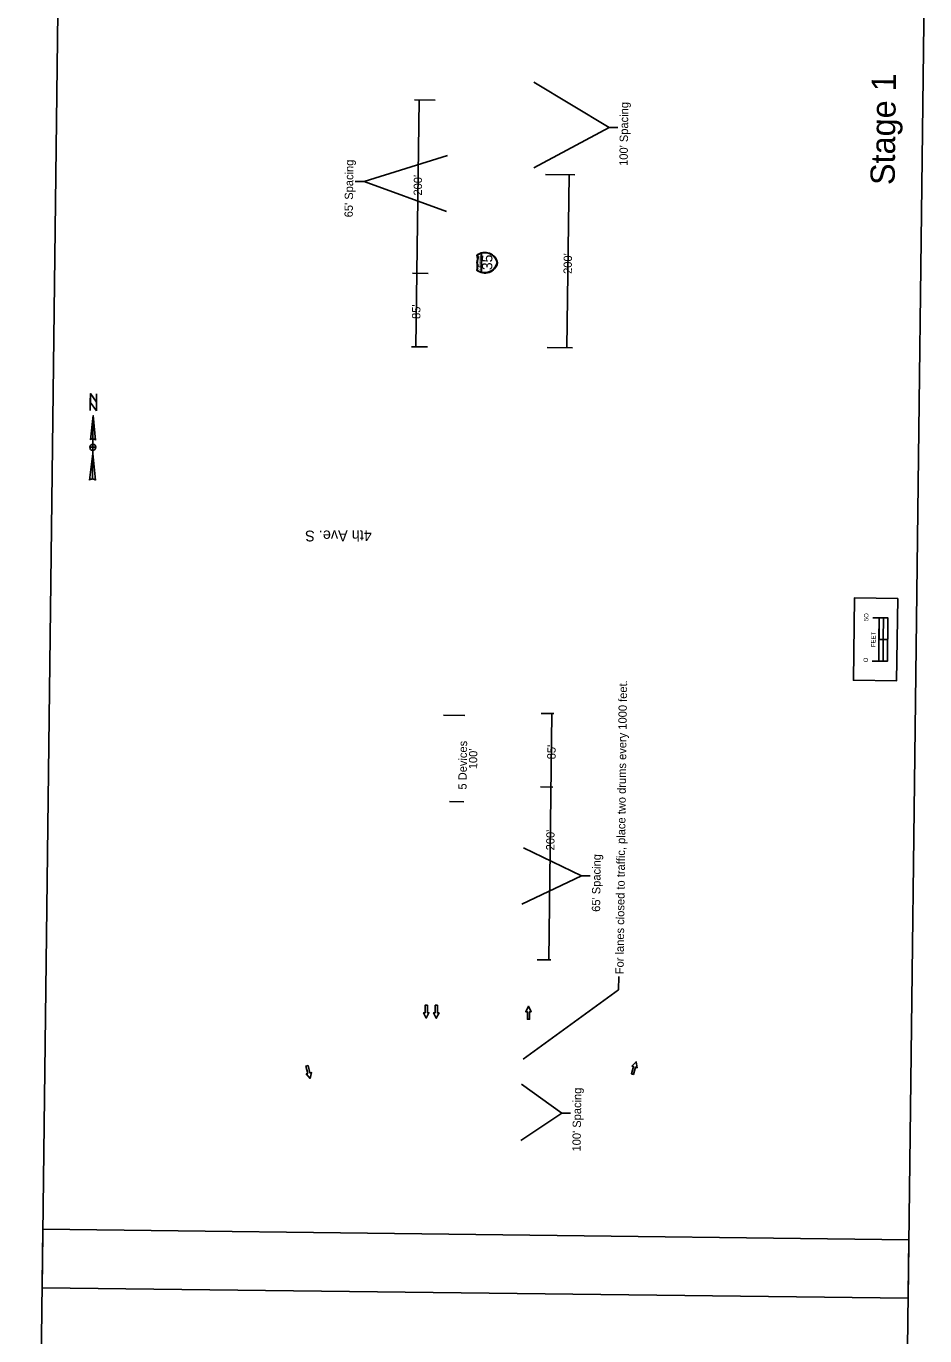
# Model space of a CAD drawing. Extents: x 4959127 to 4960275, y 3872379 to 3884458.
# Drawn here: x 4959145 to 4960183, y 3875336 to 3876849 of the extents above; entities that cross this region are included whole.
import ezdxf

# ---------------------------------------------------------------- set-up
doc = ezdxf.new("R2010")
doc.units = 0
for name, color, linetype in [('Cell', 7, 'Continuous'), ('dsnCellElements', 7, 'Continuous'), ('dsnCellsHighwaySymbols', 7, 'Continuous'), ('dsnCellsScaleBlock', 7, 'Continuous'), ('Level 2', 7, 'Continuous'), ('Level 5', 7, 'Continuous'), ('NamedBoundary', 7, 'Continuous'), ('SheetText', 7, 'Continuous'), ('Text', 7, 'Continuous')]:
    doc.layers.add(name, color=color, linetype=linetype)

msp = doc.modelspace()

# ---------------------------------------------------------------- linework, layer by layer
at = {"layer": 'Cell'}
for p, q in [((4959222.7, 3876398.7), (4959221.8, 3876325.5)), ((4959222.7, 3876398.7), (4959225.1, 3876370.5)), ((4959219.5, 3876370.6), (4959219.5, 3876370.6)), ((4959219.6, 3876370.9), (4959220.2, 3876371.4)), ((4959218.2, 3876324.1), (4959222.1, 3876355.1)), ((4959222.2, 3876358.6), (4959222.2, 3876358.6))]:
    msp.add_line(p, q, dxfattribs=at)
for points in [[(4959219.2, 3876404.4), (4959219.5, 3876424.1), (4959226.4, 3876414.2), (4959226.5, 3876424)], [(4959219.5, 3876370.6), (4959222.7, 3876398.7), (4959222.3, 3876372)], [(4959222.2, 3876358.6), (4959222.2, 3876362.1), (4959218.7, 3876362.2)], [(4959221.8, 3876325.5), (4959222.1, 3876355.1), (4959225.3, 3876324)], [(4959225.7, 3876362.1), (4959222.2, 3876362.1), (4959222.3, 3876365.6)]]:
    msp.add_lwpolyline(points, dxfattribs=at)
msp.add_lwpolyline([(4959226.3, 3876404.3), (4959219.3, 3876414.3), (4959219.5, 3876424.1), (4959226.4, 3876414.2)], close=True, dxfattribs=at)
for centre, radius, start, end in [((4959222.3, 3876368.5), 3.52, 89.3179, 142.4233), ((4959222.3, 3876368.5), 3.52, 36.1456, 89.3194), ((4959222.2, 3876362.1), 3.52, 89.2975, 179.2975), ((4959222.2, 3876362.1), 3.52, 179.2975, 269.2975), ((4959222.2, 3876362.1), 3.52, 269.2975, 359.2975), ((4959222.2, 3876362.1), 3.52, 359.2975, 89.2975), ((4959221.7, 3876320.4), 5.1, 89.2869, 132.9165), ((4959221.7, 3876320.4), 5.11, 45.6996, 89.2982)]:
    msp.add_arc(centre, radius, start, end, dxfattribs=at)
at = {"layer": 'dsnCellElements'}
msp.add_lwpolyline([(4960100.3, 3876093), (4960101.5, 3876188), (4960151.5, 3876187.4), (4960150.3, 3876092.4)], close=True, dxfattribs=at)
msp.add_lwpolyline([(4960100.3, 3876093), (4960101.5, 3876188), (4960151.5, 3876187.4), (4960150.3, 3876092.4)], close=True, dxfattribs=at)
at = {"layer": 'dsnCellsHighwaySymbols'}
for p, q in [((4959670.6, 3876586.2), (4959670.4, 3876564.5)), ((4959670.9, 3876564.3), (4959671.1, 3876586.3))]:
    msp.add_line(p, q, dxfattribs=at)
for centre, radius, start, end in [((4959651.2, 3876580), 15, 342.3065, 16.2887), ((4959674.8, 3876572.3), 15, 10.8347, 127.6287), ((4959651.2, 3876580), 15.5, 342.7231, 14.8585), ((4959674.8, 3876572.3), 14.5, 106.5608, 126.3017), ((4959674.8, 3876572.3), 14.5, 11.2271, 104.5442), ((4959651.1, 3876571.2), 15, 342.3065, 16.2887), ((4959674.8, 3876578.3), 15, 230.9665, 347.7605), ((4959651.1, 3876571.2), 15.5, 343.7366, 15.8721), ((4959674.8, 3876578.3), 14.5, 232.2935, 252.0342), ((4959674.8, 3876578.3), 14.5, 254.051, 347.368)]:
    msp.add_arc(centre, radius, start, end, dxfattribs=at)
at = {"layer": 'dsnCellsScaleBlock'}
msp.add_line((4960139.9, 3876140), (4960129.9, 3876140.1), dxfattribs=at)
msp.add_line((4960139.9, 3876140), (4960129.9, 3876140.1), dxfattribs=at)
for points in [[(4960150.3, 3876092.4), (4960100.3, 3876093), (4960101.5, 3876188), (4960151.5, 3876187.4)], [(4960134.9, 3876140.1), (4960135.2, 3876165.1), (4960130.2, 3876165.1), (4960129.9, 3876140.1)], [(4960139.6, 3876115), (4960139.9, 3876140), (4960134.9, 3876140.1), (4960134.6, 3876115.1)]]:
    msp.add_lwpolyline(points, close=True, dxfattribs=at)
for points in [[(4960122.1, 3876115.2), (4960139.6, 3876115), (4960140.2, 3876165), (4960122.7, 3876165.2)], [(4960129.6, 3876115.2), (4960130.2, 3876165.1)]]:
    msp.add_lwpolyline(points, dxfattribs=at)
at = {"layer": 'Level 2'}
for points in [[(4959606.1, 3875717.7), (4959608.6, 3875717.6), (4959608.5, 3875708.9), (4959610.3, 3875708.9), (4959607.1, 3875702.6), (4959604.1, 3875708.9), (4959606, 3875708.9)], [(4959617.6, 3875717.5), (4959620.1, 3875717.5), (4959620, 3875708.7), (4959621.9, 3875708.7), (4959618.7, 3875702.5), (4959615.6, 3875708.8), (4959617.5, 3875708.8)], [(4959726.4, 3875701.3), (4959723.9, 3875701.4), (4959724, 3875710.1), (4959722.1, 3875710.1), (4959725.3, 3875716.4), (4959728.3, 3875710.1), (4959726.5, 3875710.1)], [(4959468.3, 3875647.2), (4959470.8, 3875647.8), (4959472.8, 3875639.3), (4959474.7, 3875639.7), (4959473.1, 3875632.9), (4959468.6, 3875638.2), (4959470.4, 3875638.7)], [(4959846.4, 3875637.6), (4959844, 3875638.3), (4959846.5, 3875646.7), (4959844.7, 3875647.2), (4959849.5, 3875652.3), (4959850.7, 3875645.4), (4959848.9, 3875646)]]:
    msp.add_lwpolyline(points, close=True, dxfattribs=at)
at = {"layer": 'Level 5'}
for points in [[(4959606, 3875708.9), (4959604.1, 3875708.9), (4959607.1, 3875702.6), (4959610.3, 3875708.9), (4959608.5, 3875708.9), (4959608.6, 3875717.6), (4959606.1, 3875717.7), (4959606, 3875708.9)], [(4959617.5, 3875708.8), (4959615.6, 3875708.8), (4959618.7, 3875702.5), (4959621.9, 3875708.7), (4959620, 3875708.7), (4959620.1, 3875717.5), (4959617.6, 3875717.5), (4959617.5, 3875708.8)], [(4959726.5, 3875710.1), (4959728.3, 3875710.1), (4959725.3, 3875716.4), (4959722.1, 3875710.1), (4959724, 3875710.1), (4959723.9, 3875701.4), (4959726.4, 3875701.3), (4959726.5, 3875710.1)], [(4959470.4, 3875638.7), (4959468.6, 3875638.2), (4959473.1, 3875632.9), (4959474.7, 3875639.7), (4959472.8, 3875639.3), (4959470.8, 3875647.8), (4959468.3, 3875647.2), (4959470.4, 3875638.7)], [(4959848.9, 3875646), (4959850.7, 3875645.4), (4959849.5, 3875652.3), (4959844.7, 3875647.2), (4959846.5, 3875646.7), (4959844, 3875638.3), (4959846.4, 3875637.6), (4959848.9, 3875646)]]:
    msp.add_lwpolyline(points, dxfattribs=at)
at = {"layer": 'NamedBoundary'}
for points in [[(4959163.7, 3875391.2), (4960163.6, 3875379), (4960182.8, 3876946.3), (4959182.9, 3876958.6)], [(4959145.3, 3873891.3), (4960145.2, 3873879.1), (4960164.4, 3875446.5), (4959164.5, 3875458.7)]]:
    msp.add_lwpolyline(points, close=True, dxfattribs=at)
at = {"layer": 'SheetText'}
for p, q in [((4959818.2, 3876731.6), (4959731.5, 3876783.9)), ((4959617.6, 3876763.2), (4959593.6, 3876763.5)), ((4959595.3, 3876478.2), (4959598.8, 3876763.4)), ((4959744.8, 3876677.4), (4959778.6, 3876676.9)), ((4959769.6, 3876477), (4959772, 3876677)), ((4959609.5, 3876563), (4959591.2, 3876563.2)), ((4959608.5, 3876478), (4959590.1, 3876478.3)), ((4959746.6, 3876477.3), (4959776.1, 3876476.9)), ((4959627.2, 3876052.6), (4959651.7, 3876052.3)), ((4959739.8, 3876054.7), (4959754.6, 3876054.5)), ((4959748.7, 3875769.9), (4959752.2, 3876054.5)), ((4959739.2, 3875969.7), (4959753.5, 3875969.5)), ((4959634, 3875952.9), (4959650.5, 3875952.7)), ((4959735.2, 3875770.1), (4959751.1, 3875769.9))]:
    msp.add_line(p, q, dxfattribs=at)
for points in [[(4959828.3, 3876731.4), (4959818.2, 3876731.6), (4959731.2, 3876684.9)], [(4959535.3, 3876669), (4959631.6, 3876699.2)], [(4959525.2, 3876669.2), (4959535.3, 3876669), (4959630.5, 3876634.3)], [(4959786.4, 3875867.1), (4959786.4, 3875867.1), (4959719.3, 3875899.4)], [(4959796.4, 3875867), (4959786.4, 3875867.1), (4959717.7, 3875834.4)], [(4959829.5, 3875750.6), (4959829.3, 3875735.5), (4959719.1, 3875655.4)], [(4959763.9, 3875592.9), (4959763.9, 3875592.9), (4959717.3, 3875626.2)], [(4959773.9, 3875592.8), (4959763.9, 3875592.9), (4959716.5, 3875561.2)]]:
    msp.add_lwpolyline(points, dxfattribs=at)

# ---------------------------------------------------------------- texts
at = {"layer": 'dsnCellsHighwaySymbols'}
for s, height, p in [('A', 2.5, (4959670, 3876578.5)), ('T', 2.5, (4959670, 3876577.1)), ('E', 2.5, (4959670.1, 3876581.9)), ('T', 2.5, (4959670.1, 3876580.2)), ('35', 12, (4959683.4, 3876566.7)), ('T', 2.5, (4959669.9, 3876570.2)), ('N', 2.5, (4959669.9, 3876568.4)), ('I', 2.5, (4959669.9, 3876567.5)), ('S', 2.5, (4959670, 3876575.3)), ('R', 2.5, (4959670, 3876573.6)), ('E', 2.5, (4959669.9, 3876571.9))]:
    msp.add_text(s, height=height, rotation=89.2975, dxfattribs=at).set_placement(p)
at = {"layer": 'dsnCellsScaleBlock'}
for s, p in [('5O', (4960117.6, 3876161.2)), ('FEET', (4960125.8, 3876131.2)), ('O', (4960117.1, 3876113.7))]:
    msp.add_text(s, height=5, rotation=89.2975, dxfattribs=at).set_placement(p)
at = {"layer": 'SheetText'}
for s, height, rotation, p in [("100' Spacing", 9.6, 89.3042, (4959839.7, 3876687.1)), ("65' Spacing", 9.6, 89.2908, (4959522.3, 3876627.7)), ("200'", 9.6, 89.2975, (4959602.1, 3876652.8)), ("200'", 9.6, 89.2975, (4959775.2, 3876562.3)), ("85'", 9.6, 89.2975, (4959600.3, 3876510.3)), ('4th Ave. S', 12.48, 180.2975, (4959544.3, 3876266.2)), ('For lanes closed to traffic, place two drums every 1000 feet.', 9.6, 89.3042, (4959835, 3875753.3)), ('5 Devices', 9.6, 89.3042, (4959653.7, 3875966.6)), ("85'", 9.6, 89.2975, (4959756.4, 3876001.6)), ("100'", 9.6, 89.3042, (4959665.9, 3875990.1)), ("200'", 9.6, 89.2975, (4959755.1, 3875896.4)), ("65' Spacing", 9.6, 89.3042, (4959807.9, 3875825.4)), ("100' Spacing", 9.6, 89.3042, (4959785.4, 3875548.5))]:
    msp.add_text(s, height=height, rotation=rotation, dxfattribs=at).set_placement(p)
at = {"layer": 'Text'}
msp.add_text('Stage 1', height=28, rotation=89.2975, dxfattribs=at).set_placement((4960148, 3876664.9))

doc.saveas('drawing.dxf')
